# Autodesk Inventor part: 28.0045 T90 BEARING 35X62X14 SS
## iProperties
Created: 2006-02
Part Number: 28.0045 T90 BEARING 35X62X14 SS
Material: Stainless Steel
Description: Rolling bearings: ball bearings cylindrical and spherical roller bearings- Specification for dimensions of ball bearings, cylindrical and spherical roller beari
Document SubType Name: Modeling
Standard: BS 292: Part 1
Designer: Andy Moles
Standards Organization: BSI
Language: en-US
Size Designation: 7007 - 35 x 62 x 14
Categories: <MemberInstance><Categories><Category DisplayName="Shaft Parts" InternalName="7f7aeb1f-a693-4053-b835-cee3144e0d98" Mnemonic="SHFT"><Category DisplayName="Beari
Mass: 141.354 g
Surface Area: 124.618 cm^2
Volume: 17.4943 cm^3
Density: 8.08 g/cm^3
Author: Andy Moles
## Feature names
1. Body [Revolution]
2. Fillet1
3. Ball [Revolution]
4. Balls [Circular Pattern]
